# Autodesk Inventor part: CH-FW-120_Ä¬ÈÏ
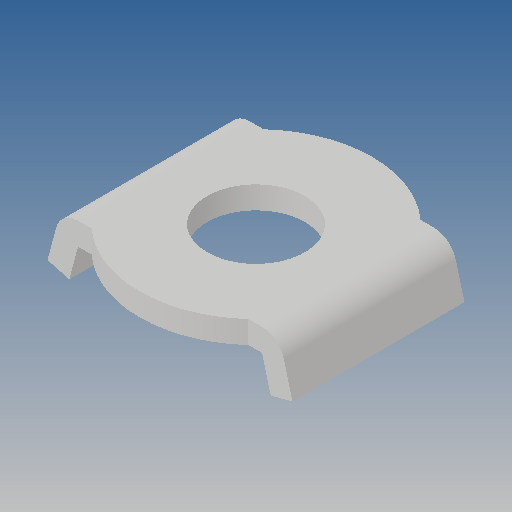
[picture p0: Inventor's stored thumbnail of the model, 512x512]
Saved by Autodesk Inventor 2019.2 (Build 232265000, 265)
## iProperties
Created: 2010-06
Part Number: CH-FW-120_Ä¬ÈÏ
Material: Ogólny
Document SubType Name: Modeling
Designer: CADENGINEERING4
Density: 1 g/cm^3
Appearance: Domyślna
Author: CADENGINEERING4
Revision Number: ÈÎºÎ
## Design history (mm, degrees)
feature "NONE"
node "Bryła1"
